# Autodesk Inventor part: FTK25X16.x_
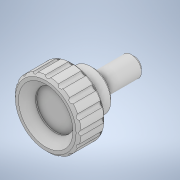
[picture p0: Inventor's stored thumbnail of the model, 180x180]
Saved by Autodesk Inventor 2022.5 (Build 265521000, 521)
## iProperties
Created: 2023-10
Part Number: FTK25X16.x_
Material: 一般
Document SubType Name: Modeling
Designer: ImaoCorp
Density: 1 g/cm^3
Appearance: 既定
Sending System: SOLIDWORKS 2021-2021301
MC: AMD64
MC_MODEL: Intel64 Family 6 Model 60 Stepping 3, GenuineIntel
OS: Windows_NT
FRU: Parasolid Version 32.1, build 255,  1- 1-2021
FORMAT: text
GUISE: transmit
KEY: FTK25X16
FILE: FTK25X16.x_t
DATE: Tue Oct 17 11:07:52 2023
Author: ImaoCorp
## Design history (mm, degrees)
feature "Base1"
node "ソリッド1"
